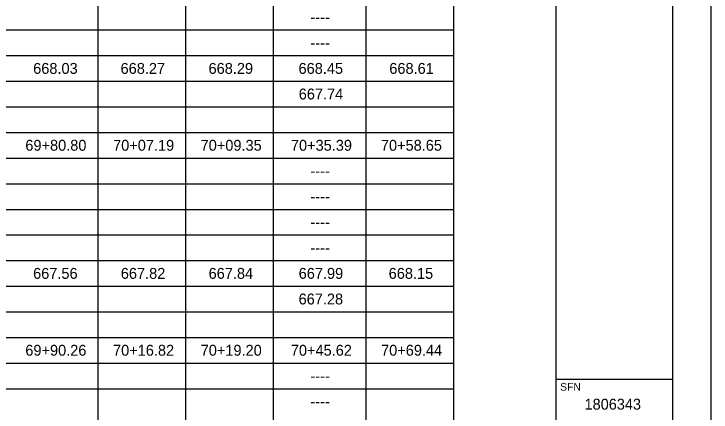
# Model space of a CAD drawing. Extents: x 0 to 34, y 0 to 22.
# Drawn here: x 24.99 to 34, y 5.07 to 10.21 of the extents above; entities that cross this region are included whole.
import ezdxf

# ---------------------------------------------------------------- set-up
doc = ezdxf.new("R2010")
doc.units = 0
for name, color, linetype in [('SH_Border', 7, 'Continuous'), ('SH_Cut_Line', 7, 'Continuous'), ('SH_Data', 7, 'Continuous'), ('SH_Text', 7, 'Continuous')]:
    doc.layers.add(name, color=color, linetype=linetype)

msp = doc.modelspace()

# ---------------------------------------------------------------- linework, layer by layer
at = {"layer": 'SH_Border'}
for p, q in [((32, 0.5), (32, 21.5)), ((32, 5.5), (33.5, 5.5))]:
    msp.add_line(p, q, dxfattribs=at)
msp.add_lwpolyline([(1.5, 21.5), (33.5, 21.5), (33.5, 0.5), (1.5, 0.5)], close=True, dxfattribs=at)
at = {"layer": 'SH_Cut_Line'}
msp.add_lwpolyline([(0, 0), (34, 0), (34, 22), (0, 22)], close=True, dxfattribs=at)
at = {"layer": 'SH_Text'}
for p, q in [((30.6725, 21.2971), (30.6725, 2.3971)), ((26.078, 20.1135), (26.078, 2.3971)), ((27.2107, 20.1135), (27.2107, 2.3971)), ((28.3434, 20.1135), (28.3434, 2.3971)), ((29.5398, 20.1135), (29.5398, 2.3971)), ((4.1998, 10.008), (30.6725, 10.008)), ((4.1998, 9.6771), (30.6725, 9.6771)), ((4.1998, 9.3462), (30.6725, 9.3462)), ((2.7998, 9.0153), (30.6725, 9.0153)), ((2.7998, 8.6844), (30.6725, 8.6844)), ((4.1998, 8.3535), (30.6725, 8.3535)), ((4.1998, 8.0226), (30.6725, 8.0226)), ((4.1998, 7.6916), (30.6725, 7.6916)), ((4.1998, 7.3607), (30.6725, 7.3607)), ((4.1998, 7.0298), (30.6725, 7.0298)), ((4.1998, 6.6989), (30.6725, 6.6989)), ((2.7998, 6.368), (30.6725, 6.368)), ((2.7998, 6.0371), (30.6725, 6.0371)), ((4.1998, 5.7062), (30.6725, 5.7062)), ((4.1998, 5.3753), (30.6725, 5.3753))]:
    msp.add_line(p, q, dxfattribs=at)

# ---------------------------------------------------------------- texts
at = {"layer": 'SH_Data'}
for s, height, p in [('SFN', 0.1, (32.05, 5.35)), ('1806343', 0.14, (32.3656, 5.105))]:
    msp.add_text(s, height=height, dxfattribs=at).set_placement(p)
at = {"layer": 'SH_Text'}
for s, p in [('----', (28.8239, 10.1032)), ('----', (28.8239, 9.7723)), ('668.03', (25.2415, 9.4414)), ('668.27', (26.3708, 9.4414)), ('668.29', (27.5074, 9.4414)), ('668.45', (28.6701, 9.4414)), ('668.61', (29.8429, 9.4414)), ('667.74', (28.6726, 9.1105)), ('69+80.80', (25.1401, 8.4487)), ('70+07.19', (26.274, 8.4487)), ('70+09.35', (27.4049, 8.4487)), ('70+35.39', (28.5713, 8.4487)), ('70+58.65', (29.734, 8.4487)), ('----', (28.8239, 8.1178)), ('----', (28.8239, 7.7868)), ('----', (28.8239, 7.4559)), ('----', (28.8239, 7.125)), ('667.56', (25.2405, 6.7941)), ('667.82', (26.3738, 6.7941)), ('667.84', (27.5081, 6.7941)), ('667.99', (28.672, 6.7941)), ('668.15', (29.8347, 6.7941)), ('667.28', (28.6708, 6.4632)), ('69+90.26', (25.1399, 5.8014)), ('70+16.82', (26.2731, 5.8014)), ('70+19.20', (27.4055, 5.8014)), ('70+45.62', (28.5704, 5.8014)), ('70+69.44', (29.7365, 5.8014)), ('----', (28.8239, 5.4705)), ('----', (28.8239, 5.1396))]:
    msp.add_text(s, height=0.14051, dxfattribs=at).set_placement(p)

doc.saveas('drawing.dxf')
